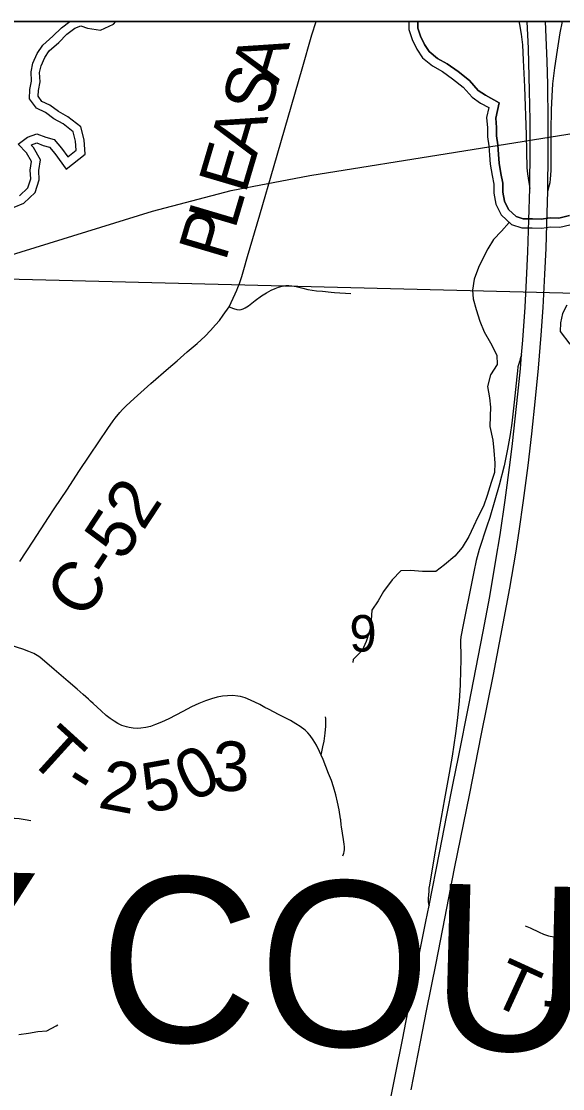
# Model space of a CAD drawing. Extents: x 0 to 34, y 0 to 22.
# Drawn here: x 6.964 to 7.584, y 20.15 to 21.373 of the extents above; entities that cross this region are included whole.
import ezdxf

# ---------------------------------------------------------------- set-up
doc = ezdxf.new("R2010")
doc.units = 0
for name, color, linetype in [('GM_X_Corporation', 7, 'Continuous'), ('GM_X_County_Road', 7, 'Continuous'), ('GM_X_County_Road_Text', 7, 'Continuous'), ('GM_X_County_Text', 7, 'Continuous'), ('GM_X_Interchange_Ramps', 7, 'Continuous'), ('GM_X_Interstate_Route', 7, 'Continuous'), ('GM_X_Major_River', 7, 'Continuous'), ('GM_X_Minor_River', 7, 'Continuous'), ('GM_X_Rail_Line', 7, 'Continuous'), ('GM_X_Section_Text', 7, 'Continuous'), ('GM_X_Township_Road', 7, 'Continuous'), ('GM_X_Township_Road_Text', 7, 'Continuous'), ('SH_Text', 7, 'Continuous')]:
    doc.layers.add(name, color=color, linetype=linetype)

msp = doc.modelspace()

# ---------------------------------------------------------------- linework, layer by layer
at = {"layer": 'GM_X_Corporation'}
for points in [[(4.7823, 18.128), (4.7905, 18.3604), (4.8074, 19.5455), (4.8169, 20.042), (4.8194, 20.1261), (5.11, 20.116), (6.0551, 20.0845), (6.4901, 20.0752), (6.7204, 20.0659), (7.3691, 20.0515), (7.3901, 20.051), (7.814, 20.0425), (8.4311, 20.028), (8.4311, 21.3734), (1.6311, 21.3734)], [(4.0508, 18.1454), (4.7823, 18.128), (4.7905, 18.3604), (4.8074, 19.5455), (4.8169, 20.042), (4.8194, 20.1261), (5.11, 20.116), (6.0551, 20.0845), (6.4901, 20.0752), (6.7204, 20.0659), (7.3691, 20.0515), (7.3901, 20.051), (7.814, 20.0425), (8.4311, 20.028), (8.4311, 21.3734), (2.7987, 21.3734)]]:
    msp.add_lwpolyline(points, dxfattribs=at)
for points in [[(7.88, 21.3734), (6.8607, 21.3734), (6.8544, 21.0806), (7.8729, 21.0548)], [(7.8729, 21.0548), (7.8512, 20.0413), (6.8338, 20.0683), (6.8544, 21.0806)]]:
    msp.add_lwpolyline(points, close=True, dxfattribs=at)
at = {"layer": 'GM_X_County_Road'}
for points in [[(7.2186, 21.0891), (7.2228, 21.104), (7.2368, 21.1517), (7.2532, 21.2083), (7.2853, 21.3191), (7.2966, 21.3579), (7.3015, 21.3733), (7.3016, 21.3734)], [(7.2016, 21.0462), (7.2087, 21.0611), (7.2105, 21.0652), (7.2117, 21.0685), (7.2134, 21.0729), (7.2161, 21.0808), (7.2178, 21.0863), (7.2186, 21.0891)], [(6.9617, 20.7542), (6.977, 20.7776), (6.9948, 20.8046), (7.0012, 20.8145), (7.0163, 20.8373), (7.0295, 20.8576), (7.0421, 20.8761), (7.0525, 20.8916), (7.0625, 20.9066), (7.0688, 20.9157), (7.0711, 20.9187), (7.0762, 20.9249), (7.0795, 20.9285), (7.0838, 20.9329), (7.0929, 20.9413), (7.112, 20.9582), (7.1322, 20.9757), (7.1421, 20.9842), (7.1537, 20.9945), (7.165, 21.0043), (7.1742, 21.0127), (7.1804, 21.0189), (7.1862, 21.0254), (7.1906, 21.0307), (7.195, 21.0368), (7.2016, 21.0462)]]:
    msp.add_lwpolyline(points, dxfattribs=at)
at = {"layer": 'GM_X_Interchange_Ramps'}
for points in [[(7.5337, 21.3734), (7.5345, 21.3697), (7.5364, 21.3587), (7.5377, 21.3463), (7.5388, 21.3289), (7.54, 21.2985), (7.5419, 21.2432), (7.543, 21.2054), (7.5434, 21.2019), (7.5437, 21.1988), (7.5444, 21.1937), (7.5452, 21.1885), (7.5461, 21.182)], [(7.5668, 21.1789), (7.5687, 21.1859), (7.5695, 21.1888), (7.5701, 21.1925), (7.5706, 21.2024), (7.5707, 21.2198), (7.5707, 21.2484), (7.571, 21.272), (7.5717, 21.2875), (7.5728, 21.3017), (7.5749, 21.3202), (7.5778, 21.3405), (7.5811, 21.3601), (7.5838, 21.3734)], [(7.5368, 20.9911), (7.5353, 20.9865), (7.5344, 20.9836), (7.5336, 20.9809), (7.5327, 20.9774), (7.532, 20.9729), (7.5312, 20.9661), (7.5285, 20.937), (7.5256, 20.9129), (7.5238, 20.9), (7.5207, 20.8829), (7.5168, 20.864), (7.5111, 20.8418), (7.5063, 20.8244), (7.5003, 20.8048), (7.4971, 20.7947), (7.4884, 20.7682), (7.4848, 20.7556), (7.482, 20.7423), (7.4794, 20.7289), (7.4704, 20.6838), (7.4672, 20.6679), (7.4667, 20.6636), (7.4667, 20.6593), (7.4671, 20.6487), (7.4672, 20.64), (7.467, 20.6301), (7.4663, 20.6127), (7.4651, 20.5947), (7.4633, 20.575), (7.4611, 20.5571), (7.4571, 20.5313), (7.4538, 20.5117), (7.4486, 20.4823), (7.4372, 20.4181), (7.4311, 20.3833), (7.4306, 20.38), (7.4304, 20.3763), (7.4298, 20.3679), (7.4298, 20.3664), (7.4299, 20.3641), (7.4302, 20.362), (7.4308, 20.3601)]]:
    msp.add_lwpolyline(points, dxfattribs=at)
at = {"layer": 'GM_X_Interstate_Route'}
for points in [[(7.3805, 20.1066), (7.3927, 20.1682), (7.4002, 20.206), (7.413, 20.2712), (7.4222, 20.3169), (7.427, 20.3415), (7.4308, 20.3601), (7.4427, 20.4205), (7.4512, 20.4637), (7.4584, 20.5003), (7.4644, 20.5301), (7.4762, 20.5898), (7.4928, 20.6739), (7.5003, 20.7142), (7.5074, 20.7559), (7.5121, 20.7847), (7.5179, 20.8247), (7.5238, 20.8678), (7.5265, 20.8894), (7.5327, 20.9462), (7.5355, 20.9753), (7.5368, 20.9911), (7.5381, 21.0081), (7.5408, 21.0459), (7.5425, 21.0769), (7.544, 21.1092), (7.5453, 21.1459), (7.5461, 21.182), (7.5462, 21.1856), (7.5466, 21.2235), (7.5465, 21.2602), (7.546, 21.2938), (7.5446, 21.3422), (7.5433, 21.3734)], [(7.4101, 20.1489), (7.421, 20.2038), (7.4279, 20.2391), (7.4388, 20.2939), (7.4488, 20.3452), (7.4601, 20.4025), (7.4774, 20.4883), (7.4905, 20.5547), (7.5045, 20.6248), (7.5159, 20.6833), (7.5233, 20.7236), (7.5302, 20.764), (7.5342, 20.7891), (7.5391, 20.8242), (7.5443, 20.8642), (7.5486, 20.9006), (7.5529, 20.9413), (7.5562, 20.976), (7.5593, 21.0137), (7.5614, 21.0453), (7.5635, 21.0837), (7.5649, 21.1129), (7.5659, 21.1408), (7.5668, 21.1789), (7.567, 21.1893), (7.5673, 21.2129), (7.5673, 21.2588), (7.5668, 21.3011), (7.566, 21.3278), (7.5641, 21.3734)]]:
    msp.add_lwpolyline(points, dxfattribs=at)
at = {"layer": 'GM_X_Major_River'}
for points in [[(6.9551, 21.1605), (6.9665, 21.165), (6.9795, 21.1772), (6.9841, 21.1916), (6.9836, 21.2023), (6.9854, 21.2146), (6.9773, 21.2288), (6.9747, 21.2315), (6.9752, 21.2319), (6.9811, 21.234), (6.9885, 21.2311), (6.9956, 21.2292), (7.0017, 21.2221), (7.0147, 21.2039), (7.0367, 21.2212), (7.0354, 21.2375), (7.0316, 21.2525), (7.0169, 21.264), (7.0062, 21.27), (6.9963, 21.2774), (6.9871, 21.2816), (6.9827, 21.2876), (6.9831, 21.294), (6.985, 21.304), (6.9845, 21.3148), (6.9862, 21.3225), (6.9903, 21.3319), (6.9955, 21.3396), (7.0063, 21.3493), (7.0158, 21.3586), (7.0248, 21.3655), (7.0315, 21.3683), (7.0394, 21.3656), (7.0542, 21.3632), (7.0692, 21.37), (7.0718, 21.3734)], [(6.9551, 21.1605), (6.9665, 21.165), (6.9795, 21.1772), (6.9841, 21.1916), (6.9836, 21.2023), (6.9854, 21.2146), (6.9773, 21.2288), (6.9747, 21.2315), (6.9752, 21.2319), (6.9811, 21.234), (6.9885, 21.2311), (6.9956, 21.2292), (7.0017, 21.2221), (7.0147, 21.2039), (7.0367, 21.2212), (7.0354, 21.2375), (7.0316, 21.2525), (7.0169, 21.264), (7.0062, 21.27), (6.9963, 21.2774), (6.9871, 21.2816), (6.9827, 21.2876), (6.9831, 21.294), (6.985, 21.304), (6.9845, 21.3148), (6.9862, 21.3225), (6.9903, 21.3319), (6.9955, 21.3396), (7.0063, 21.3493), (7.0158, 21.3586), (7.0248, 21.3655), (7.0315, 21.3683), (7.0394, 21.3656), (7.0542, 21.3632), (7.0692, 21.37), (7.0718, 21.3734)], [(6.9612, 21.1735), (6.9709, 21.1827), (6.9742, 21.1929), (6.9737, 21.2028), (6.9752, 21.2126), (6.9694, 21.2228), (6.9599, 21.2326), (6.9704, 21.2406), (6.9813, 21.2445), (6.9916, 21.2405), (7.001, 21.2379), (7.0094, 21.2282), (7.0167, 21.218), (7.0265, 21.2257), (7.0256, 21.2359), (7.0229, 21.2469), (7.0115, 21.2558), (7.0008, 21.2618), (6.9913, 21.2689), (6.9807, 21.2737), (6.9727, 21.2846), (6.9733, 21.2952), (6.9751, 21.3047), (6.9747, 21.3157), (6.9768, 21.3256), (6.9817, 21.3366), (6.988, 21.3461), (6.9996, 21.3565), (7.0094, 21.3661), (7.0189, 21.3734)], [(7.4077, 21.3734), (7.4075, 21.3642), (7.4113, 21.3525), (7.4167, 21.3415), (7.4232, 21.3317), (7.4347, 21.3224), (7.4461, 21.3161), (7.4578, 21.3075), (7.47, 21.2981), (7.48, 21.2865), (7.4898, 21.2798), (7.4993, 21.2746), (7.4968, 21.2632), (7.4976, 21.2514), (7.4977, 21.2412), (7.4993, 21.2306), (7.5002, 21.22), (7.5007, 21.2098), (7.503, 21.1969), (7.505, 21.1867), (7.5051, 21.1765), (7.5075, 21.164), (7.5133, 21.1516), (7.5251, 21.1407), (7.5372, 21.1367), (7.5489, 21.1368), (7.5599, 21.1362), (7.5701, 21.1378), (7.5807, 21.1375), (7.592, 21.1403)], [(7.4181, 21.3734), (7.4179, 21.3657), (7.421, 21.3564), (7.4257, 21.3467), (7.431, 21.3388), (7.4405, 21.331), (7.4516, 21.3248), (7.4641, 21.3158), (7.4772, 21.3057), (7.4869, 21.2943), (7.4953, 21.2886), (7.5112, 21.2799), (7.5072, 21.2624), (7.508, 21.2519), (7.5081, 21.242), (7.5097, 21.2318), (7.5105, 21.2207), (7.511, 21.211), (7.5132, 21.1989), (7.5154, 21.1878), (7.5155, 21.1775), (7.5174, 21.1672), (7.5218, 21.1578), (7.5305, 21.1499), (7.5388, 21.1471), (7.5492, 21.1472), (7.5594, 21.1466), (7.5694, 21.1482), (7.5796, 21.1479), (7.5918, 21.1509)], [(7.5918, 21.1509), (7.5796, 21.1479), (7.5694, 21.1482), (7.5594, 21.1466), (7.5492, 21.1472), (7.5388, 21.1471), (7.5305, 21.1499), (7.5218, 21.1578), (7.5174, 21.1672), (7.5155, 21.1775), (7.5154, 21.1878), (7.5132, 21.1989), (7.511, 21.211), (7.5105, 21.2207), (7.5097, 21.2318), (7.5081, 21.242), (7.508, 21.2519), (7.5072, 21.2624), (7.5112, 21.2799), (7.4953, 21.2886), (7.4869, 21.2943), (7.4772, 21.3057), (7.4641, 21.3158), (7.4516, 21.3248), (7.4405, 21.331), (7.431, 21.3388), (7.4257, 21.3467), (7.421, 21.3564), (7.4179, 21.3657), (7.4181, 21.3734)], [(7.5886, 21.0482), (7.5838, 21.0387), (7.5816, 21.028), (7.581, 21.0178), (7.5921, 21.0035)]]:
    msp.add_lwpolyline(points, dxfattribs=at)
at = {"layer": 'GM_X_Minor_River'}
for points in [[(7.5227, 21.1429), (7.5138, 21.133), (7.5048, 21.1235), (7.4981, 21.1128), (7.4922, 21.101), (7.4873, 21.0914), (7.4825, 21.0778), (7.4804, 21.0652), (7.4812, 21.0554), (7.4847, 21.0433), (7.489, 21.0297), (7.494, 21.0176), (7.5013, 21.0048), (7.5086, 20.9909), (7.5087, 20.9799), (7.5013, 20.9681), (7.4976, 20.9548), (7.5, 20.9419), (7.5012, 20.9313), (7.5009, 20.9207), (7.5006, 20.909), (7.5038, 20.8935), (7.505, 20.8817), (7.5063, 20.867), (7.5056, 20.8564), (7.502, 20.8449), (7.4975, 20.8301), (7.4931, 20.8176), (7.4868, 20.805), (7.4816, 20.7943), (7.4764, 20.7829), (7.4686, 20.7703), (7.4604, 20.7604), (7.4483, 20.7504), (7.4386, 20.7428), (7.4231, 20.743), (7.4095, 20.744), (7.3985, 20.7435), (7.3884, 20.7331), (7.3787, 20.7198), (7.3723, 20.7091), (7.3652, 20.6984), (7.3646, 20.687), (7.3628, 20.6757), (7.3588, 20.6627), (7.3543, 20.6521), (7.3438, 20.6421), (7.3435, 20.6387)], [(6.9608, 20.2123), (6.9718, 20.2135), (6.9824, 20.2155), (6.9929, 20.2164), (7.0035, 20.2222), (7.0053, 20.2233)]]:
    msp.add_lwpolyline(points, dxfattribs=at)
at = {"layer": 'GM_X_Rail_Line'}
msp.add_lwpolyline([(6.5645, 20.9858), (7.1137, 21.1558), (7.204, 21.1794), (7.2943, 21.1968), (7.6279, 21.2502), (7.7336, 21.2656), (7.828, 21.2769), (7.8989, 21.2789), (7.9605, 21.282), (7.9997, 21.2894), (8.0776, 21.3189), (8.1287, 21.3314), (8.3607, 21.3631), (8.4311, 21.373)], dxfattribs=at)
at = {"layer": 'GM_X_Township_Road'}
for points in [[(7.2016, 21.0462), (7.2068, 21.0441), (7.2106, 21.0431), (7.2131, 21.0429), (7.2156, 21.0432), (7.2179, 21.0439), (7.2201, 21.045), (7.2237, 21.0475), (7.2316, 21.0535), (7.2386, 21.0586), (7.2444, 21.0623), (7.2498, 21.0653), (7.2543, 21.0673), (7.2584, 21.0688), (7.2625, 21.0699), (7.2668, 21.0705), (7.27, 21.0708), (7.2736, 21.0704), (7.2784, 21.0695), (7.286, 21.0675), (7.2919, 21.0661), (7.297, 21.0652), (7.3017, 21.0647), (7.3088, 21.064), (7.3187, 21.0629), (7.3224, 21.0625), (7.3413, 21.0616)], [(7.012, 20.6214), (7.0012, 20.6304), (6.9847, 20.6445), (6.9817, 20.6466), (6.9778, 20.6487), (6.9721, 20.6512), (6.9651, 20.6537), (6.9519, 20.6582), (6.9451, 20.6606)], [(7.3072, 20.5322), (7.3051, 20.5365), (7.3016, 20.5436), (7.2981, 20.5498), (7.2946, 20.5547), (7.292, 20.5578), (7.2886, 20.561), (7.2831, 20.5652), (7.278, 20.5684), (7.2718, 20.5722), (7.2589, 20.5785), (7.2466, 20.5852), (7.2427, 20.5871), (7.2367, 20.5902), (7.2262, 20.5955), (7.2199, 20.5981), (7.2145, 20.5996), (7.2115, 20.6001), (7.206, 20.6007), (7.1998, 20.6005), (7.1942, 20.5998), (7.1881, 20.5987), (7.1815, 20.5969), (7.1745, 20.5946), (7.167, 20.5915), (7.1585, 20.5876), (7.1486, 20.5825), (7.1327, 20.574), (7.1243, 20.57), (7.1173, 20.5673), (7.1114, 20.5653), (7.106, 20.564), (7.1005, 20.5632), (7.0968, 20.563), (7.0918, 20.5631), (7.0869, 20.5639), (7.0839, 20.5646), (7.0786, 20.5665), (7.0741, 20.5686), (7.0698, 20.5711), (7.0652, 20.5742), (7.0608, 20.5776), (7.0548, 20.583), (7.0458, 20.5914), (7.0426, 20.5943), (7.0404, 20.5964), (7.0344, 20.6018), (7.0273, 20.6078), (7.017, 20.6168), (7.012, 20.6214)], [(7.3072, 20.5322), (7.3091, 20.5418), (7.3104, 20.5485), (7.3116, 20.5577), (7.3123, 20.5657), (7.3125, 20.5707), (7.3124, 20.5744), (7.3122, 20.5763)], [(7.3318, 20.4168), (7.3327, 20.419), (7.3331, 20.42), (7.3335, 20.4217), (7.3338, 20.4241), (7.3338, 20.4271), (7.3334, 20.4302), (7.3326, 20.4356), (7.3315, 20.4429), (7.3305, 20.4502), (7.3302, 20.4526), (7.3295, 20.4582), (7.3293, 20.4594), (7.3276, 20.4698), (7.3259, 20.4783), (7.3239, 20.4867), (7.3212, 20.4962), (7.3188, 20.5032), (7.3157, 20.5112), (7.3093, 20.5272), (7.3072, 20.5322)], [(6.9495, 20.46), (6.9525, 20.46), (6.9555, 20.46), (6.9611, 20.4596), (6.9678, 20.4587), (6.9745, 20.4576)], [(7.541, 20.3368), (7.5467, 20.3343), (7.5568, 20.3295), (7.5619, 20.3273), (7.5678, 20.3254), (7.5739, 20.324), (7.58, 20.3232), (7.5874, 20.3225)]]:
    msp.add_lwpolyline(points, dxfattribs=at)
at = {"layer": 'SH_Text'}
msp.add_line((1.6311, 21.3734), (8.4311, 21.373), dxfattribs=at)

# ---------------------------------------------------------------- texts
at = {"layer": 'GM_X_County_Road_Text'}
for s, height, rotation, p in [('A', 0.0568, 73.5007, (7.2575, 21.3001)), ('S', 0.0568, 73.5044, (7.2466, 21.2633)), ('A', 0.0568, 73.5082, (7.2324, 21.2154)), ('E', 0.0568, 73.506, (7.2203, 21.1746)), ('L', 0.0568, 73.5047, (7.2083, 21.1339)), ('P', 0.0568, 73.5044, (7.1974, 21.0971)), ('C-52', 0.05682, 56.6824, (7.0359, 20.6861))]:
    msp.add_text(s, height=height, rotation=rotation, dxfattribs=at).set_placement(p)
at = {"layer": 'GM_X_County_Text'}
msp.add_text('GUERNSEY COUNTY', height=0.189394, rotation=358.543, dxfattribs=at).set_placement((5.5592, 20.2436))
at = {"layer": 'GM_X_Section_Text'}
msp.add_text('9', height=0.0419, rotation=0, dxfattribs=at).set_placement((7.3395, 20.651))
at = {"layer": 'GM_X_Township_Road_Text'}
for s, rotation, p in [('T', 317.7541, (6.9688, 20.5285)), ('0', 26.3936, (7.158, 20.4775)), ('3', 359.3443, (7.1825, 20.4915)), ('5', 10.1897, (7.107, 20.4658)), ('2', 349.1835, (7.05, 20.4725)), ('-', 327.7845, (7.0089, 20.4934)), ('T', 335.3979, (7.498, 20.2491)), ('-', 356.3824, (7.5585, 20.226))]:
    msp.add_text(s, height=0.0568, rotation=rotation, dxfattribs=at).set_placement(p)

doc.saveas('drawing.dxf')
